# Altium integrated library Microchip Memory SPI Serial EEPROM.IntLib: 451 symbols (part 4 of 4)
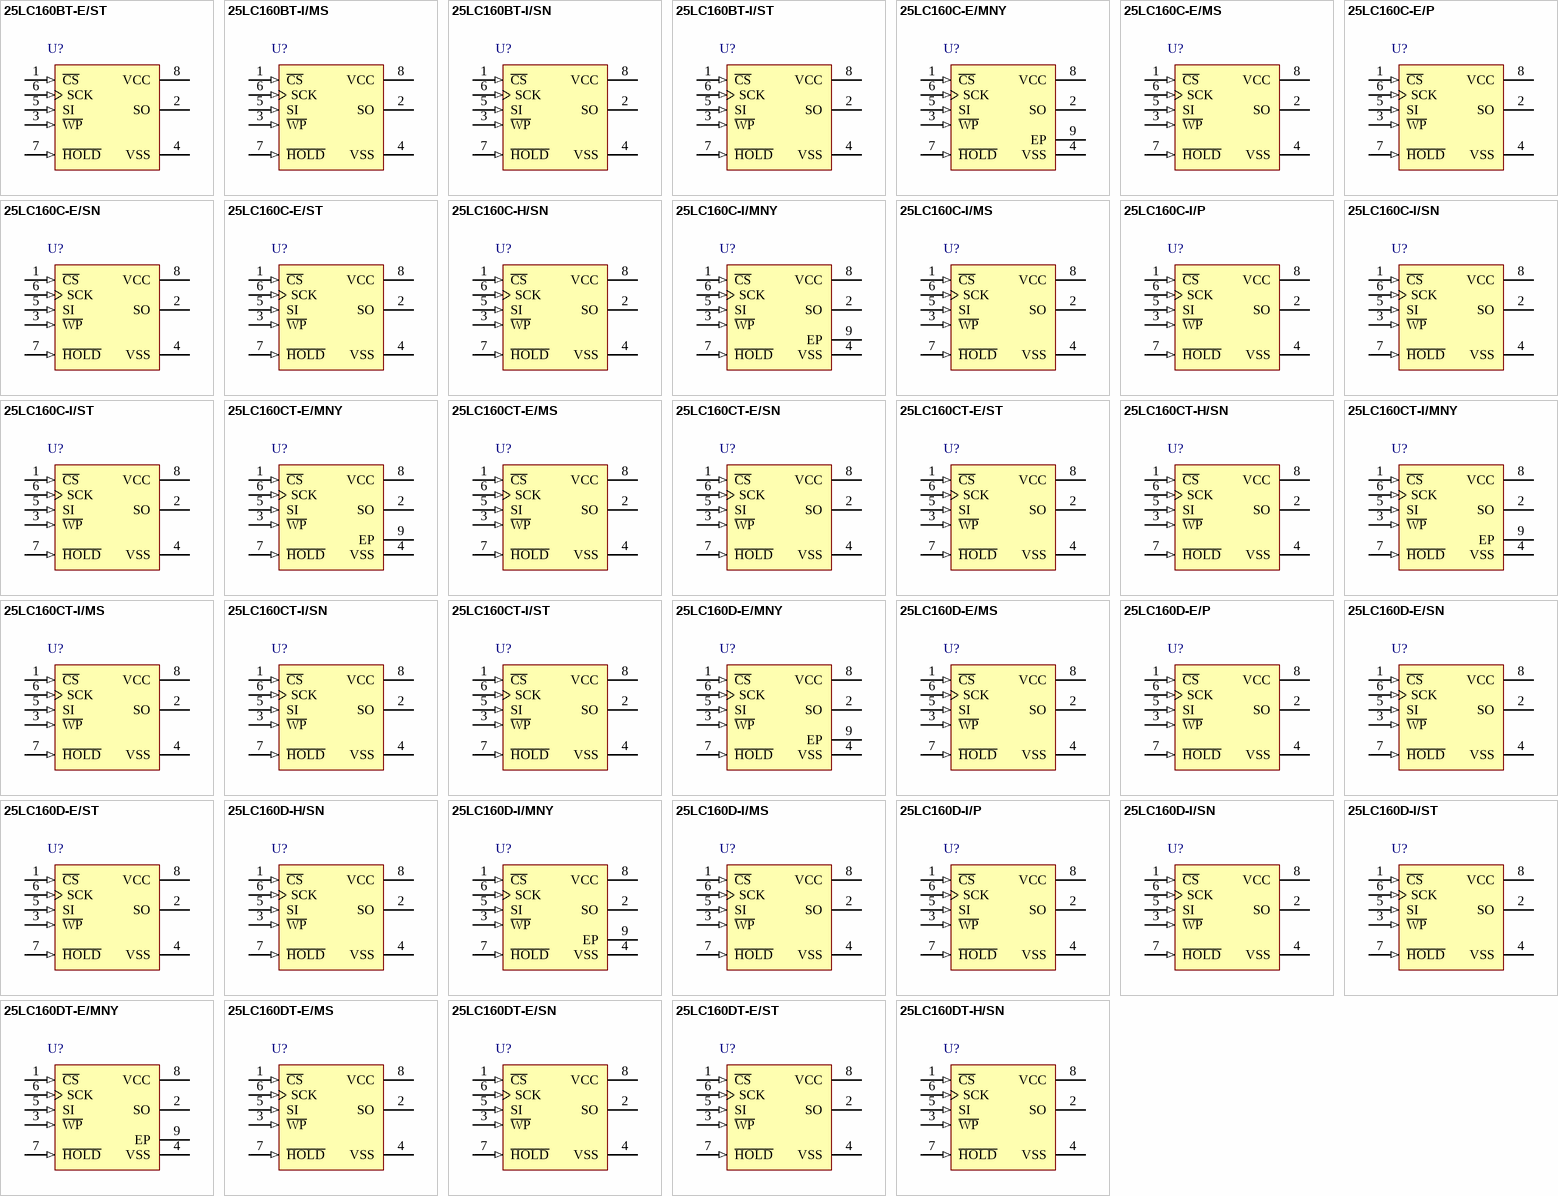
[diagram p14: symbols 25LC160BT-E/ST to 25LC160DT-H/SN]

## 25LC160C-I/ST
designator U?
16K SPI Bus Serial EEPROM, 8-Pin TSSO, Industrial Temperature
footprint TSSOP-ST8_N (TSOP, 8-Leads, Body 3x4.4mm, Pitch 0.65mm, IPC Medium Density)
footprint TSSOP-ST8_L (TSOP, 8-Leads, Body 3x4.4mm, Pitch 0.65mm, IPC High Density)
footprint TSSOP-ST8_M (TSOP, 8-Leads, Body 3x4.4mm, Pitch 0.65mm, IPC Low Density)
pins: 1 ~{CS} (in), 2 SO (hiz), 3 ~{WP} (in), 4 VSS (power), 5 SI (in), 6 SCK (in), 7 ~{HOLD} (in), 8 VCC (power)

## 25LC160CT-E/MNY
designator U?
16K SPI Bus Serial EEPROM, 8-Pin TDFN, Automotive Temperature, Tape and Reel
footprint TDFN-MN8 (SON, 8-Leads, Body 2x3mm, Pitch 0.5mm, Microchip Recommended)
pins: 1 ~{CS} (in), 2 SO (hiz), 3 ~{WP} (in), 4 VSS (power), 5 SI (in), 6 SCK (in), 7 ~{HOLD} (in), 8 VCC (power), 9 EP

## 25LC160CT-E/MS
designator U?
16K SPI Bus Serial EEPROM, 8-Pin MSOP, Automotive Temperature, Tape and Reel
footprint MSOP-MS8_N (TSOP, 8-Leads, Body 3x3mm, Pitch 0.65mm, IPC Medium Density)
footprint MSOP-MS8_L (TSOP, 8-Leads, Body 3x3mm, Pitch 0.65mm, IPC High Density)
footprint MSOP-MS8_M (TSOP, 8-Leads, Body 3x3mm, Pitch 0.65mm, IPC Low Density)
pins: 1 ~{CS} (in), 2 SO (hiz), 3 ~{WP} (in), 4 VSS (power), 5 SI (in), 6 SCK (in), 7 ~{HOLD} (in), 8 VCC (power)

## 25LC160CT-E/SN
designator U?
16K SPI Bus Serial EEPROM, 8-Pin SOIC, Automotive Temperature, Tape and Reel
footprint SOIC-SN8_N (SOIC, 8-Leads, Body 4.9x3.8mm, Pitch 1.27mm, IPC Medium Density)
footprint SOIC-SN8_L (SOIC, 8-Leads, Body 4.9x3.8mm, Pitch 1.27mm, IPC High Density)
footprint SOIC-SN8_M (SOIC, 8-Leads, Body 4.9x3.8mm, Pitch 1.27mm, IPC Low Density)
pins: 1 ~{CS} (in), 2 SO (hiz), 3 ~{WP} (in), 4 VSS (power), 5 SI (in), 6 SCK (in), 7 ~{HOLD} (in), 8 VCC (power)

## 25LC160CT-E/ST
designator U?
16K SPI Bus Serial EEPROM, 8-Pin TSSO, Automotive Temperature, Tape and Reel
footprint TSSOP-ST8_N (TSOP, 8-Leads, Body 3x4.4mm, Pitch 0.65mm, IPC Medium Density)
footprint TSSOP-ST8_L (TSOP, 8-Leads, Body 3x4.4mm, Pitch 0.65mm, IPC High Density)
footprint TSSOP-ST8_M (TSOP, 8-Leads, Body 3x4.4mm, Pitch 0.65mm, IPC Low Density)
pins: 1 ~{CS} (in), 2 SO (hiz), 3 ~{WP} (in), 4 VSS (power), 5 SI (in), 6 SCK (in), 7 ~{HOLD} (in), 8 VCC (power)

## 25LC160CT-H/SN
designator U?
16K SPI Bus Serial EEPROM, 8-Pin SOIC, Extended (High) Temperature, Tape and Reel
footprint SOIC-SN8_N (SOIC, 8-Leads, Body 4.9x3.8mm, Pitch 1.27mm, IPC Medium Density)
footprint SOIC-SN8_L (SOIC, 8-Leads, Body 4.9x3.8mm, Pitch 1.27mm, IPC High Density)
footprint SOIC-SN8_M (SOIC, 8-Leads, Body 4.9x3.8mm, Pitch 1.27mm, IPC Low Density)
pins: 1 ~{CS} (in), 2 SO (hiz), 3 ~{WP} (in), 4 VSS (power), 5 SI (in), 6 SCK (in), 7 ~{HOLD} (in), 8 VCC (power)

## 25LC160CT-I/MNY
designator U?
16K SPI Bus Serial EEPROM, 8-Pin TDFN, Industrial Temperature, Tape and Reel
footprint TDFN-MN8 (SON, 8-Leads, Body 2x3mm, Pitch 0.5mm, Microchip Recommended)
pins: 1 ~{CS} (in), 2 SO (hiz), 3 ~{WP} (in), 4 VSS (power), 5 SI (in), 6 SCK (in), 7 ~{HOLD} (in), 8 VCC (power), 9 EP

## 25LC160CT-I/MS
designator U?
16K SPI Bus Serial EEPROM, 8-Pin MSOP, Industrial Temperature, Tape and Reel
footprint MSOP-MS8_N (TSOP, 8-Leads, Body 3x3mm, Pitch 0.65mm, IPC Medium Density)
footprint MSOP-MS8_L (TSOP, 8-Leads, Body 3x3mm, Pitch 0.65mm, IPC High Density)
footprint MSOP-MS8_M (TSOP, 8-Leads, Body 3x3mm, Pitch 0.65mm, IPC Low Density)
pins: 1 ~{CS} (in), 2 SO (hiz), 3 ~{WP} (in), 4 VSS (power), 5 SI (in), 6 SCK (in), 7 ~{HOLD} (in), 8 VCC (power)

## 25LC160CT-I/SN
designator U?
16K SPI Bus Serial EEPROM, 8-Pin SOIC, Industrial Temperature, Tape and Reel
footprint SOIC-SN8_N (SOIC, 8-Leads, Body 4.9x3.8mm, Pitch 1.27mm, IPC Medium Density)
footprint SOIC-SN8_L (SOIC, 8-Leads, Body 4.9x3.8mm, Pitch 1.27mm, IPC High Density)
footprint SOIC-SN8_M (SOIC, 8-Leads, Body 4.9x3.8mm, Pitch 1.27mm, IPC Low Density)
pins: 1 ~{CS} (in), 2 SO (hiz), 3 ~{WP} (in), 4 VSS (power), 5 SI (in), 6 SCK (in), 7 ~{HOLD} (in), 8 VCC (power)

## 25LC160CT-I/ST
designator U?
16K SPI Bus Serial EEPROM, 8-Pin TSSO, Industrial Temperature, Tape and Reel
footprint TSSOP-ST8_N (TSOP, 8-Leads, Body 3x4.4mm, Pitch 0.65mm, IPC Medium Density)
footprint TSSOP-ST8_L (TSOP, 8-Leads, Body 3x4.4mm, Pitch 0.65mm, IPC High Density)
footprint TSSOP-ST8_M (TSOP, 8-Leads, Body 3x4.4mm, Pitch 0.65mm, IPC Low Density)
pins: 1 ~{CS} (in), 2 SO (hiz), 3 ~{WP} (in), 4 VSS (power), 5 SI (in), 6 SCK (in), 7 ~{HOLD} (in), 8 VCC (power)

## 25LC160D-E/MNY
designator U?
16K SPI Bus Serial EEPROM, 8-Pin TDFN, Automotive Temperature
footprint TDFN-MN8 (SON, 8-Leads, Body 2x3mm, Pitch 0.5mm, Microchip Recommended)
pins: 1 ~{CS} (in), 2 SO (hiz), 3 ~{WP} (in), 4 VSS (power), 5 SI (in), 6 SCK (in), 7 ~{HOLD} (in), 8 VCC (power), 9 EP

## 25LC160D-E/MS
designator U?
16K SPI Bus Serial EEPROM, 8-Pin MSOP, Automotive Temperature
footprint MSOP-MS8_N (TSOP, 8-Leads, Body 3x3mm, Pitch 0.65mm, IPC Medium Density)
footprint MSOP-MS8_L (TSOP, 8-Leads, Body 3x3mm, Pitch 0.65mm, IPC High Density)
footprint MSOP-MS8_M (TSOP, 8-Leads, Body 3x3mm, Pitch 0.65mm, IPC Low Density)
pins: 1 ~{CS} (in), 2 SO (hiz), 3 ~{WP} (in), 4 VSS (power), 5 SI (in), 6 SCK (in), 7 ~{HOLD} (in), 8 VCC (power)

## 25LC160D-E/P
designator U?
16K SPI Bus Serial EEPROM, 8-Pin PDIP, Automotive Temperature
footprint PDIP300-P8 (DIP, 8-Leads, Row Spacing 7.62mm, Pitch 2.54mm, Body 9.5x6.6mm)
pins: 1 ~{CS} (in), 2 SO (hiz), 3 ~{WP} (in), 4 VSS (power), 5 SI (in), 6 SCK (in), 7 ~{HOLD} (in), 8 VCC (power)

## 25LC160D-E/SN
designator U?
16K SPI Bus Serial EEPROM, 8-Pin SOIC, Automotive Temperature
footprint SOIC-SN8_N (SOIC, 8-Leads, Body 4.9x3.8mm, Pitch 1.27mm, IPC Medium Density)
footprint SOIC-SN8_L (SOIC, 8-Leads, Body 4.9x3.8mm, Pitch 1.27mm, IPC High Density)
footprint SOIC-SN8_M (SOIC, 8-Leads, Body 4.9x3.8mm, Pitch 1.27mm, IPC Low Density)
pins: 1 ~{CS} (in), 2 SO (hiz), 3 ~{WP} (in), 4 VSS (power), 5 SI (in), 6 SCK (in), 7 ~{HOLD} (in), 8 VCC (power)

## 25LC160D-E/ST
designator U?
16K SPI Bus Serial EEPROM, 8-Pin TSSO, Automotive Temperature
footprint TSSOP-ST8_N (TSOP, 8-Leads, Body 3x4.4mm, Pitch 0.65mm, IPC Medium Density)
footprint TSSOP-ST8_L (TSOP, 8-Leads, Body 3x4.4mm, Pitch 0.65mm, IPC High Density)
footprint TSSOP-ST8_M (TSOP, 8-Leads, Body 3x4.4mm, Pitch 0.65mm, IPC Low Density)
pins: 1 ~{CS} (in), 2 SO (hiz), 3 ~{WP} (in), 4 VSS (power), 5 SI (in), 6 SCK (in), 7 ~{HOLD} (in), 8 VCC (power)

## 25LC160D-H/SN
designator U?
16K SPI Bus Serial EEPROM, 8-Pin SOIC, Extended (High) Temperature
footprint SOIC-SN8_N (SOIC, 8-Leads, Body 4.9x3.8mm, Pitch 1.27mm, IPC Medium Density)
footprint SOIC-SN8_L (SOIC, 8-Leads, Body 4.9x3.8mm, Pitch 1.27mm, IPC High Density)
footprint SOIC-SN8_M (SOIC, 8-Leads, Body 4.9x3.8mm, Pitch 1.27mm, IPC Low Density)
pins: 1 ~{CS} (in), 2 SO (hiz), 3 ~{WP} (in), 4 VSS (power), 5 SI (in), 6 SCK (in), 7 ~{HOLD} (in), 8 VCC (power)

## 25LC160D-I/MNY
designator U?
16K SPI Bus Serial EEPROM, 8-Pin TDFN, Industrial Temperature
footprint TDFN-MN8 (SON, 8-Leads, Body 2x3mm, Pitch 0.5mm, Microchip Recommended)
pins: 1 ~{CS} (in), 2 SO (hiz), 3 ~{WP} (in), 4 VSS (power), 5 SI (in), 6 SCK (in), 7 ~{HOLD} (in), 8 VCC (power), 9 EP

## 25LC160D-I/MS
designator U?
16K SPI Bus Serial EEPROM, 8-Pin MSOP, Industrial Temperature
footprint MSOP-MS8_N (TSOP, 8-Leads, Body 3x3mm, Pitch 0.65mm, IPC Medium Density)
footprint MSOP-MS8_L (TSOP, 8-Leads, Body 3x3mm, Pitch 0.65mm, IPC High Density)
footprint MSOP-MS8_M (TSOP, 8-Leads, Body 3x3mm, Pitch 0.65mm, IPC Low Density)
pins: 1 ~{CS} (in), 2 SO (hiz), 3 ~{WP} (in), 4 VSS (power), 5 SI (in), 6 SCK (in), 7 ~{HOLD} (in), 8 VCC (power)

## 25LC160D-I/P
designator U?
16K SPI Bus Serial EEPROM, 8-Pin PDIP, Industrial Temperature
footprint PDIP300-P8 (DIP, 8-Leads, Row Spacing 7.62mm, Pitch 2.54mm, Body 9.5x6.6mm)
pins: 1 ~{CS} (in), 2 SO (hiz), 3 ~{WP} (in), 4 VSS (power), 5 SI (in), 6 SCK (in), 7 ~{HOLD} (in), 8 VCC (power)

## 25LC160D-I/SN
designator U?
16K SPI Bus Serial EEPROM, 8-Pin SOIC, Industrial Temperature
footprint SOIC-SN8_N (SOIC, 8-Leads, Body 4.9x3.8mm, Pitch 1.27mm, IPC Medium Density)
footprint SOIC-SN8_L (SOIC, 8-Leads, Body 4.9x3.8mm, Pitch 1.27mm, IPC High Density)
footprint SOIC-SN8_M (SOIC, 8-Leads, Body 4.9x3.8mm, Pitch 1.27mm, IPC Low Density)
pins: 1 ~{CS} (in), 2 SO (hiz), 3 ~{WP} (in), 4 VSS (power), 5 SI (in), 6 SCK (in), 7 ~{HOLD} (in), 8 VCC (power)

## 25LC160D-I/ST
designator U?
16K SPI Bus Serial EEPROM, 8-Pin TSSO, Industrial Temperature
footprint TSSOP-ST8_N (TSOP, 8-Leads, Body 3x4.4mm, Pitch 0.65mm, IPC Medium Density)
footprint TSSOP-ST8_L (TSOP, 8-Leads, Body 3x4.4mm, Pitch 0.65mm, IPC High Density)
footprint TSSOP-ST8_M (TSOP, 8-Leads, Body 3x4.4mm, Pitch 0.65mm, IPC Low Density)
pins: 1 ~{CS} (in), 2 SO (hiz), 3 ~{WP} (in), 4 VSS (power), 5 SI (in), 6 SCK (in), 7 ~{HOLD} (in), 8 VCC (power)

## 25LC160DT-E/MNY
designator U?
16K SPI Bus Serial EEPROM, 8-Pin TDFN, Automotive Temperature, Tape and Reel
footprint TDFN-MN8 (SON, 8-Leads, Body 2x3mm, Pitch 0.5mm, Microchip Recommended)
pins: 1 ~{CS} (in), 2 SO (hiz), 3 ~{WP} (in), 4 VSS (power), 5 SI (in), 6 SCK (in), 7 ~{HOLD} (in), 8 VCC (power), 9 EP

## 25LC160DT-E/MS
designator U?
16K SPI Bus Serial EEPROM, 8-Pin MSOP, Automotive Temperature, Tape and Reel
footprint MSOP-MS8_N (TSOP, 8-Leads, Body 3x3mm, Pitch 0.65mm, IPC Medium Density)
footprint MSOP-MS8_L (TSOP, 8-Leads, Body 3x3mm, Pitch 0.65mm, IPC High Density)
footprint MSOP-MS8_M (TSOP, 8-Leads, Body 3x3mm, Pitch 0.65mm, IPC Low Density)
pins: 1 ~{CS} (in), 2 SO (hiz), 3 ~{WP} (in), 4 VSS (power), 5 SI (in), 6 SCK (in), 7 ~{HOLD} (in), 8 VCC (power)

## 25LC160DT-E/SN
designator U?
16K SPI Bus Serial EEPROM, 8-Pin SOIC, Automotive Temperature, Tape and Reel
footprint SOIC-SN8_N (SOIC, 8-Leads, Body 4.9x3.8mm, Pitch 1.27mm, IPC Medium Density)
footprint SOIC-SN8_L (SOIC, 8-Leads, Body 4.9x3.8mm, Pitch 1.27mm, IPC High Density)
footprint SOIC-SN8_M (SOIC, 8-Leads, Body 4.9x3.8mm, Pitch 1.27mm, IPC Low Density)
pins: 1 ~{CS} (in), 2 SO (hiz), 3 ~{WP} (in), 4 VSS (power), 5 SI (in), 6 SCK (in), 7 ~{HOLD} (in), 8 VCC (power)

## 25LC160DT-E/ST
designator U?
16K SPI Bus Serial EEPROM, 8-Pin TSSO, Automotive Temperature, Tape and Reel
footprint TSSOP-ST8_N (TSOP, 8-Leads, Body 3x4.4mm, Pitch 0.65mm, IPC Medium Density)
footprint TSSOP-ST8_L (TSOP, 8-Leads, Body 3x4.4mm, Pitch 0.65mm, IPC High Density)
footprint TSSOP-ST8_M (TSOP, 8-Leads, Body 3x4.4mm, Pitch 0.65mm, IPC Low Density)
pins: 1 ~{CS} (in), 2 SO (hiz), 3 ~{WP} (in), 4 VSS (power), 5 SI (in), 6 SCK (in), 7 ~{HOLD} (in), 8 VCC (power)

## 25LC160DT-H/SN
designator U?
16K SPI Bus Serial EEPROM, 8-Pin SOIC, Extended (High) Temperature, Tape and Reel
footprint SOIC-SN8_N (SOIC, 8-Leads, Body 4.9x3.8mm, Pitch 1.27mm, IPC Medium Density)
footprint SOIC-SN8_L (SOIC, 8-Leads, Body 4.9x3.8mm, Pitch 1.27mm, IPC High Density)
footprint SOIC-SN8_M (SOIC, 8-Leads, Body 4.9x3.8mm, Pitch 1.27mm, IPC Low Density)
pins: 1 ~{CS} (in), 2 SO (hiz), 3 ~{WP} (in), 4 VSS (power), 5 SI (in), 6 SCK (in), 7 ~{HOLD} (in), 8 VCC (power)

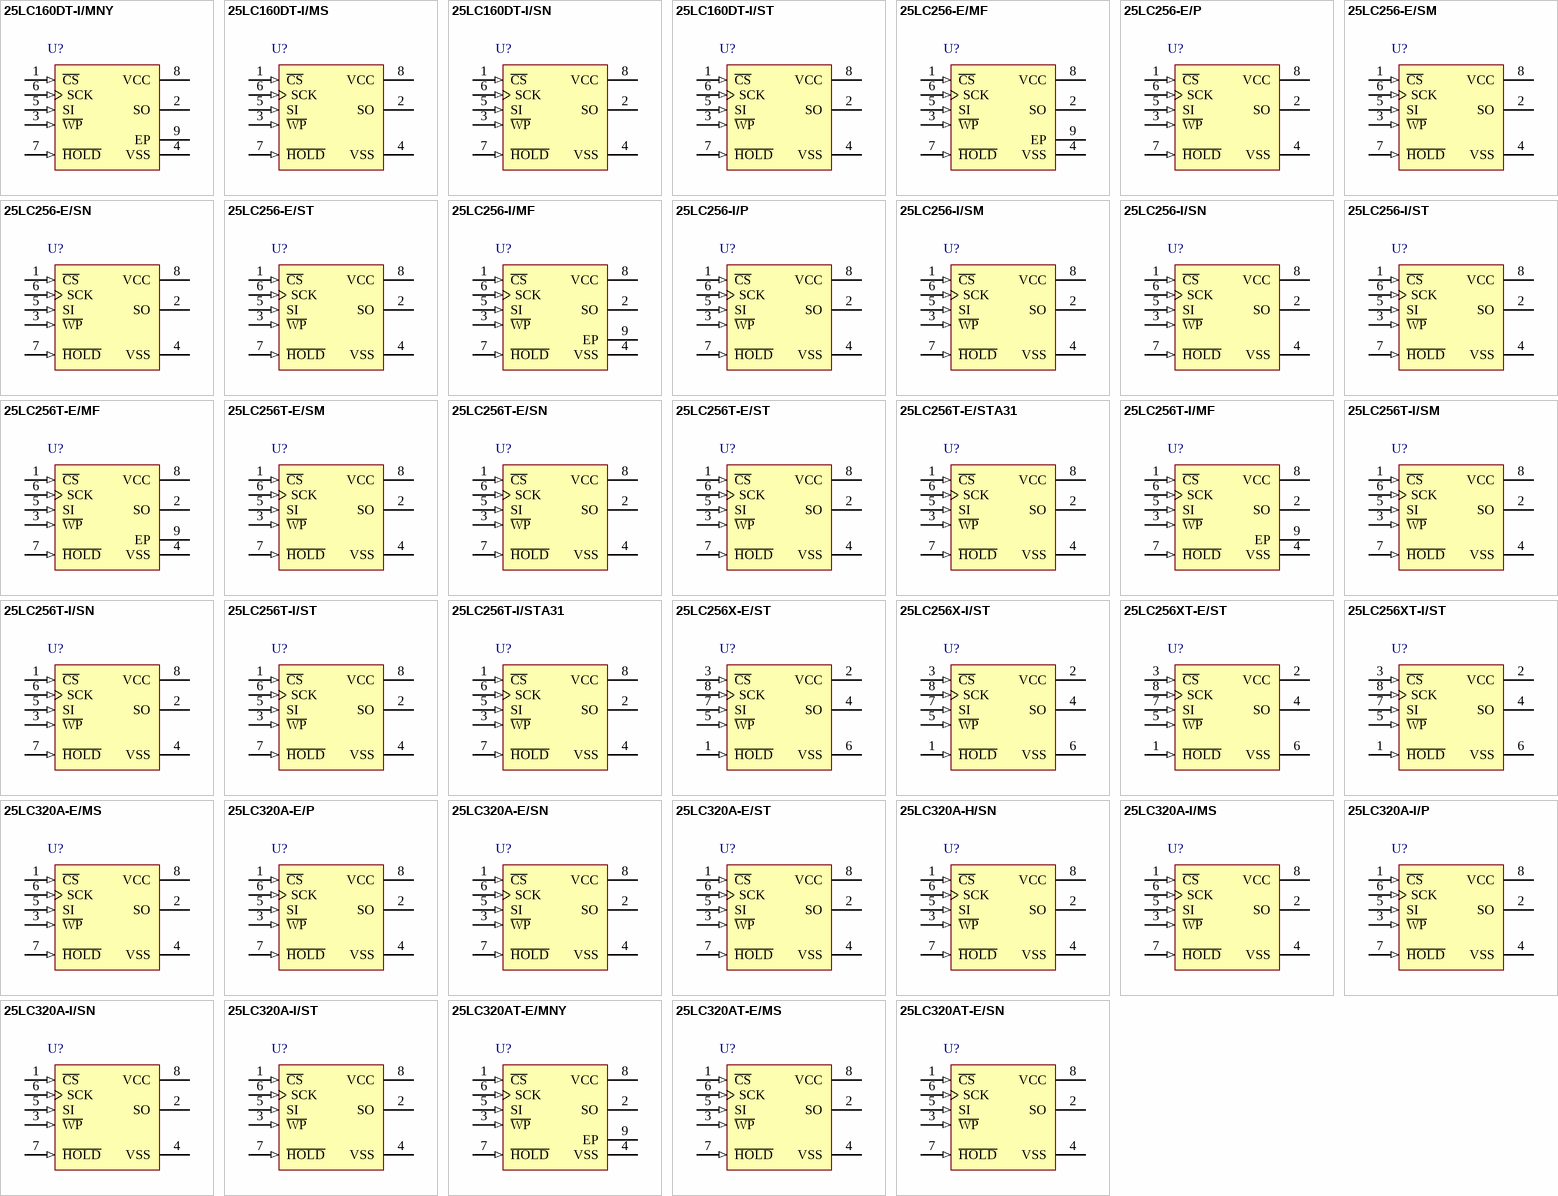
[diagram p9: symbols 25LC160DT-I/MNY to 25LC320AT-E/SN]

## 25LC160DT-I/MNY
designator U?
16K SPI Bus Serial EEPROM, 8-Pin TDFN, Industrial Temperature, Tape and Reel
footprint TDFN-MN8 (SON, 8-Leads, Body 2x3mm, Pitch 0.5mm, Microchip Recommended)
pins: 1 ~{CS} (in), 2 SO (hiz), 3 ~{WP} (in), 4 VSS (power), 5 SI (in), 6 SCK (in), 7 ~{HOLD} (in), 8 VCC (power), 9 EP

## 25LC160DT-I/MS
designator U?
16K SPI Bus Serial EEPROM, 8-Pin MSOP, Industrial Temperature, Tape and Reel
footprint MSOP-MS8_N (TSOP, 8-Leads, Body 3x3mm, Pitch 0.65mm, IPC Medium Density)
footprint MSOP-MS8_L (TSOP, 8-Leads, Body 3x3mm, Pitch 0.65mm, IPC High Density)
footprint MSOP-MS8_M (TSOP, 8-Leads, Body 3x3mm, Pitch 0.65mm, IPC Low Density)
pins: 1 ~{CS} (in), 2 SO (hiz), 3 ~{WP} (in), 4 VSS (power), 5 SI (in), 6 SCK (in), 7 ~{HOLD} (in), 8 VCC (power)

## 25LC160DT-I/SN
designator U?
16K SPI Bus Serial EEPROM, 8-Pin SOIC, Industrial Temperature, Tape and Reel
footprint SOIC-SN8_N (SOIC, 8-Leads, Body 4.9x3.8mm, Pitch 1.27mm, IPC Medium Density)
footprint SOIC-SN8_L (SOIC, 8-Leads, Body 4.9x3.8mm, Pitch 1.27mm, IPC High Density)
footprint SOIC-SN8_M (SOIC, 8-Leads, Body 4.9x3.8mm, Pitch 1.27mm, IPC Low Density)
pins: 1 ~{CS} (in), 2 SO (hiz), 3 ~{WP} (in), 4 VSS (power), 5 SI (in), 6 SCK (in), 7 ~{HOLD} (in), 8 VCC (power)

## 25LC160DT-I/ST
designator U?
16K SPI Bus Serial EEPROM, 8-Pin TSSO, Industrial Temperature, Tape and Reel
footprint TSSOP-ST8_N (TSOP, 8-Leads, Body 3x4.4mm, Pitch 0.65mm, IPC Medium Density)
footprint TSSOP-ST8_L (TSOP, 8-Leads, Body 3x4.4mm, Pitch 0.65mm, IPC High Density)
footprint TSSOP-ST8_M (TSOP, 8-Leads, Body 3x4.4mm, Pitch 0.65mm, IPC Low Density)
pins: 1 ~{CS} (in), 2 SO (hiz), 3 ~{WP} (in), 4 VSS (power), 5 SI (in), 6 SCK (in), 7 ~{HOLD} (in), 8 VCC (power)

## 25LC256-E/MF
designator U?
256K SPI Bus Serial EEPROM, 8-Pin DFN, Extended Temperature
footprint DFNS-MF8_PS (SON, 8-Leads, Body 5x6mm, Pitch 1.27mm)
pins: 1 ~{CS} (in), 2 SO (hiz), 3 ~{WP} (in), 4 VSS (power), 5 SI (in), 6 SCK (in), 7 ~{HOLD} (in), 8 VCC (power), 9 EP

## 25LC256-E/P
designator U?
256K SPI Bus Serial EEPROM, 8-Pin PDIP, Extended Temperature
footprint PDIP300-P8 (DIP, 8-Leads, Row Spacing 7.62mm, Pitch 2.54mm, Body 9.5x6.6mm)
pins: 1 ~{CS} (in), 2 SO (hiz), 3 ~{WP} (in), 4 VSS (power), 5 SI (in), 6 SCK (in), 7 ~{HOLD} (in), 8 VCC (power)

## 25LC256-E/SM
designator U?
256K SPI Bus Serial EEPROM, 8-Pin SOIC, Extended Temperature
footprint SOIJ-SM8_N (SOP, 8-Leads, Body 5.2x5.2mm, Pitch 1.27mm, IPC Medium Density)
footprint SOIJ-SM8_L (SOP, 8-Leads, Body 5.2x5.2mm, Pitch 1.27mm, IPC High Density)
footprint SOIJ-SM8_M (SOP, 8-Leads, Body 5.2x5.2mm, Pitch 1.27mm, IPC Low Density)
pins: 1 ~{CS} (in), 2 SO (hiz), 3 ~{WP} (in), 4 VSS (power), 5 SI (in), 6 SCK (in), 7 ~{HOLD} (in), 8 VCC (power)

## 25LC256-E/SN
designator U?
256K SPI Bus Serial EEPROM, 8-Pin SOIC, Extended Temperature
footprint SOIC-SN8_N (SOIC, 8-Leads, Body 4.9x3.8mm, Pitch 1.27mm, IPC Medium Density)
footprint SOIC-SN8_L (SOIC, 8-Leads, Body 4.9x3.8mm, Pitch 1.27mm, IPC High Density)
footprint SOIC-SN8_M (SOIC, 8-Leads, Body 4.9x3.8mm, Pitch 1.27mm, IPC Low Density)
pins: 1 ~{CS} (in), 2 SO (hiz), 3 ~{WP} (in), 4 VSS (power), 5 SI (in), 6 SCK (in), 7 ~{HOLD} (in), 8 VCC (power)

## 25LC256-E/ST
designator U?
256K SPI Bus Serial EEPROM, 8-Pin TSSOP, Extended Temperature
footprint TSSOP-ST8_N (TSOP, 8-Leads, Body 3x4.4mm, Pitch 0.65mm, IPC Medium Density)
footprint TSSOP-ST8_L (TSOP, 8-Leads, Body 3x4.4mm, Pitch 0.65mm, IPC High Density)
footprint TSSOP-ST8_M (TSOP, 8-Leads, Body 3x4.4mm, Pitch 0.65mm, IPC Low Density)
pins: 1 ~{CS} (in), 2 SO (hiz), 3 ~{WP} (in), 4 VSS (power), 5 SI (in), 6 SCK (in), 7 ~{HOLD} (in), 8 VCC (power)

## 25LC256-I/MF
designator U?
256K SPI Bus Serial EEPROM, 8-Pin DFN, Industrial Temperature
footprint DFNS-MF8_PS (SON, 8-Leads, Body 5x6mm, Pitch 1.27mm)
pins: 1 ~{CS} (in), 2 SO (hiz), 3 ~{WP} (in), 4 VSS (power), 5 SI (in), 6 SCK (in), 7 ~{HOLD} (in), 8 VCC (power), 9 EP

## 25LC256-I/P
designator U?
256K SPI Bus Serial EEPROM, 8-Pin PDIP, Industrial Temperature
footprint PDIP300-P8 (DIP, 8-Leads, Row Spacing 7.62mm, Pitch 2.54mm, Body 9.5x6.6mm)
pins: 1 ~{CS} (in), 2 SO (hiz), 3 ~{WP} (in), 4 VSS (power), 5 SI (in), 6 SCK (in), 7 ~{HOLD} (in), 8 VCC (power)

## 25LC256-I/SM
designator U?
256K SPI Bus Serial EEPROM, 8-Pin SOIC, Industrial Temperature
footprint SOIJ-SM8_N (SOP, 8-Leads, Body 5.2x5.2mm, Pitch 1.27mm, IPC Medium Density)
footprint SOIJ-SM8_L (SOP, 8-Leads, Body 5.2x5.2mm, Pitch 1.27mm, IPC High Density)
footprint SOIJ-SM8_M (SOP, 8-Leads, Body 5.2x5.2mm, Pitch 1.27mm, IPC Low Density)
pins: 1 ~{CS} (in), 2 SO (hiz), 3 ~{WP} (in), 4 VSS (power), 5 SI (in), 6 SCK (in), 7 ~{HOLD} (in), 8 VCC (power)

## 25LC256-I/SN
designator U?
256K SPI Bus Serial EEPROM, 8-Pin SOIC, Industrial Temperature
footprint SOIC-SN8_N (SOIC, 8-Leads, Body 4.9x3.8mm, Pitch 1.27mm, IPC Medium Density)
footprint SOIC-SN8_L (SOIC, 8-Leads, Body 4.9x3.8mm, Pitch 1.27mm, IPC High Density)
footprint SOIC-SN8_M (SOIC, 8-Leads, Body 4.9x3.8mm, Pitch 1.27mm, IPC Low Density)
pins: 1 ~{CS} (in), 2 SO (hiz), 3 ~{WP} (in), 4 VSS (power), 5 SI (in), 6 SCK (in), 7 ~{HOLD} (in), 8 VCC (power)

## 25LC256-I/ST
designator U?
256K SPI Bus Serial EEPROM, 8-Pin TSSOP, Industrial Temperature
footprint TSSOP-ST8_N (TSOP, 8-Leads, Body 3x4.4mm, Pitch 0.65mm, IPC Medium Density)
footprint TSSOP-ST8_L (TSOP, 8-Leads, Body 3x4.4mm, Pitch 0.65mm, IPC High Density)
footprint TSSOP-ST8_M (TSOP, 8-Leads, Body 3x4.4mm, Pitch 0.65mm, IPC Low Density)
pins: 1 ~{CS} (in), 2 SO (hiz), 3 ~{WP} (in), 4 VSS (power), 5 SI (in), 6 SCK (in), 7 ~{HOLD} (in), 8 VCC (power)

## 25LC256T-E/MF
designator U?
256K SPI Bus Serial EEPROM, 8-Pin DFN, Extended Temperature, Tape and Reel
footprint DFNS-MF8_PS (SON, 8-Leads, Body 5x6mm, Pitch 1.27mm)
pins: 1 ~{CS} (in), 2 SO (hiz), 3 ~{WP} (in), 4 VSS (power), 5 SI (in), 6 SCK (in), 7 ~{HOLD} (in), 8 VCC (power), 9 EP

## 25LC256T-E/SM
designator U?
256K SPI Bus Serial EEPROM, 8-Pin SOIC, Extended Temperature, Tape and Reel
footprint SOIJ-SM8_N (SOP, 8-Leads, Body 5.2x5.2mm, Pitch 1.27mm, IPC Medium Density)
footprint SOIJ-SM8_L (SOP, 8-Leads, Body 5.2x5.2mm, Pitch 1.27mm, IPC High Density)
footprint SOIJ-SM8_M (SOP, 8-Leads, Body 5.2x5.2mm, Pitch 1.27mm, IPC Low Density)
pins: 1 ~{CS} (in), 2 SO (hiz), 3 ~{WP} (in), 4 VSS (power), 5 SI (in), 6 SCK (in), 7 ~{HOLD} (in), 8 VCC (power)

## 25LC256T-E/SN
designator U?
256K SPI Bus Serial EEPROM, 8-Pin SOIC, Extended Temperature, Tape and Reel
footprint SOIC-SN8_N (SOIC, 8-Leads, Body 4.9x3.8mm, Pitch 1.27mm, IPC Medium Density)
footprint SOIC-SN8_L (SOIC, 8-Leads, Body 4.9x3.8mm, Pitch 1.27mm, IPC High Density)
footprint SOIC-SN8_M (SOIC, 8-Leads, Body 4.9x3.8mm, Pitch 1.27mm, IPC Low Density)
pins: 1 ~{CS} (in), 2 SO (hiz), 3 ~{WP} (in), 4 VSS (power), 5 SI (in), 6 SCK (in), 7 ~{HOLD} (in), 8 VCC (power)

## 25LC256T-E/ST
designator U?
256K SPI Bus Serial EEPROM, 8-Pin TSSOP, Extended Temperature, Tape and Reel
footprint TSSOP-ST8_N (TSOP, 8-Leads, Body 3x4.4mm, Pitch 0.65mm, IPC Medium Density)
footprint TSSOP-ST8_L (TSOP, 8-Leads, Body 3x4.4mm, Pitch 0.65mm, IPC High Density)
footprint TSSOP-ST8_M (TSOP, 8-Leads, Body 3x4.4mm, Pitch 0.65mm, IPC Low Density)
pins: 1 ~{CS} (in), 2 SO (hiz), 3 ~{WP} (in), 4 VSS (power), 5 SI (in), 6 SCK (in), 7 ~{HOLD} (in), 8 VCC (power)

## 25LC256T-E/STA31
designator U?
256K SPI Bus Serial EEPROM, 8-Pin TSSOP, Extended Temperature, Tape and Reel
footprint TSSOP-ST8_N (TSOP, 8-Leads, Body 3x4.4mm, Pitch 0.65mm, IPC Medium Density)
footprint TSSOP-ST8_L (TSOP, 8-Leads, Body 3x4.4mm, Pitch 0.65mm, IPC High Density)
footprint TSSOP-ST8_M (TSOP, 8-Leads, Body 3x4.4mm, Pitch 0.65mm, IPC Low Density)
pins: 1 ~{CS} (in), 2 SO (hiz), 3 ~{WP} (in), 4 VSS (power), 5 SI (in), 6 SCK (in), 7 ~{HOLD} (in), 8 VCC (power)

## 25LC256T-I/MF
designator U?
256K SPI Bus Serial EEPROM, 8-Pin DFN, Industrial Temperature, Tape and Reel
footprint DFNS-MF8_PS (SON, 8-Leads, Body 5x6mm, Pitch 1.27mm)
pins: 1 ~{CS} (in), 2 SO (hiz), 3 ~{WP} (in), 4 VSS (power), 5 SI (in), 6 SCK (in), 7 ~{HOLD} (in), 8 VCC (power), 9 EP

## 25LC256T-I/SM
designator U?
256K SPI Bus Serial EEPROM, 8-Pin SOIC, Industrial Temperature, Tape and Reel
footprint SOIJ-SM8_N (SOP, 8-Leads, Body 5.2x5.2mm, Pitch 1.27mm, IPC Medium Density)
footprint SOIJ-SM8_L (SOP, 8-Leads, Body 5.2x5.2mm, Pitch 1.27mm, IPC High Density)
footprint SOIJ-SM8_M (SOP, 8-Leads, Body 5.2x5.2mm, Pitch 1.27mm, IPC Low Density)
pins: 1 ~{CS} (in), 2 SO (hiz), 3 ~{WP} (in), 4 VSS (power), 5 SI (in), 6 SCK (in), 7 ~{HOLD} (in), 8 VCC (power)

## 25LC256T-I/SN
designator U?
256K SPI Bus Serial EEPROM, 8-Pin SOIC, Industrial Temperature, Tape and Reel
footprint SOIC-SN8_N (SOIC, 8-Leads, Body 4.9x3.8mm, Pitch 1.27mm, IPC Medium Density)
footprint SOIC-SN8_L (SOIC, 8-Leads, Body 4.9x3.8mm, Pitch 1.27mm, IPC High Density)
footprint SOIC-SN8_M (SOIC, 8-Leads, Body 4.9x3.8mm, Pitch 1.27mm, IPC Low Density)
pins: 1 ~{CS} (in), 2 SO (hiz), 3 ~{WP} (in), 4 VSS (power), 5 SI (in), 6 SCK (in), 7 ~{HOLD} (in), 8 VCC (power)

## 25LC256T-I/ST
designator U?
256K SPI Bus Serial EEPROM, 8-Pin TSSOP, Industrial Temperature, Tape and Reel
footprint TSSOP-ST8_N (TSOP, 8-Leads, Body 3x4.4mm, Pitch 0.65mm, IPC Medium Density)
footprint TSSOP-ST8_L (TSOP, 8-Leads, Body 3x4.4mm, Pitch 0.65mm, IPC High Density)
footprint TSSOP-ST8_M (TSOP, 8-Leads, Body 3x4.4mm, Pitch 0.65mm, IPC Low Density)
pins: 1 ~{CS} (in), 2 SO (hiz), 3 ~{WP} (in), 4 VSS (power), 5 SI (in), 6 SCK (in), 7 ~{HOLD} (in), 8 VCC (power)

## 25LC256T-I/STA31
designator U?
256K SPI Bus Serial EEPROM, 8-Pin TSSOP, Industrial Temperature, Tape and Reel
footprint TSSOP-ST8_N (TSOP, 8-Leads, Body 3x4.4mm, Pitch 0.65mm, IPC Medium Density)
footprint TSSOP-ST8_L (TSOP, 8-Leads, Body 3x4.4mm, Pitch 0.65mm, IPC High Density)
footprint TSSOP-ST8_M (TSOP, 8-Leads, Body 3x4.4mm, Pitch 0.65mm, IPC Low Density)
pins: 1 ~{CS} (in), 2 SO (hiz), 3 ~{WP} (in), 4 VSS (power), 5 SI (in), 6 SCK (in), 7 ~{HOLD} (in), 8 VCC (power)

## 25LC256X-E/ST
designator U?
256K SPI Bus Serial EEPROM, 8-Pin TSSOP, Extended Temperature
footprint TSSOP-ST8_N (TSOP, 8-Leads, Body 3x4.4mm, Pitch 0.65mm, IPC Medium Density)
footprint TSSOP-ST8_L (TSOP, 8-Leads, Body 3x4.4mm, Pitch 0.65mm, IPC High Density)
footprint TSSOP-ST8_M (TSOP, 8-Leads, Body 3x4.4mm, Pitch 0.65mm, IPC Low Density)
pins: 1 ~{HOLD} (in), 2 VCC (power), 3 ~{CS} (in), 4 SO (hiz), 5 ~{WP} (in), 6 VSS (power), 7 SI (in), 8 SCK (in)

## 25LC256X-I/ST
designator U?
256K SPI Bus Serial EEPROM, 8-Pin TSSOP, Industrial Temperature
footprint TSSOP-ST8_N (TSOP, 8-Leads, Body 3x4.4mm, Pitch 0.65mm, IPC Medium Density)
footprint TSSOP-ST8_L (TSOP, 8-Leads, Body 3x4.4mm, Pitch 0.65mm, IPC High Density)
footprint TSSOP-ST8_M (TSOP, 8-Leads, Body 3x4.4mm, Pitch 0.65mm, IPC Low Density)
pins: 1 ~{HOLD} (in), 2 VCC (power), 3 ~{CS} (in), 4 SO (hiz), 5 ~{WP} (in), 6 VSS (power), 7 SI (in), 8 SCK (in)

## 25LC256XT-E/ST
designator U?
256K SPI Bus Serial EEPROM, 8-Pin TSSOP, Extended Temperature, Tape and Reel
footprint TSSOP-ST8_N (TSOP, 8-Leads, Body 3x4.4mm, Pitch 0.65mm, IPC Medium Density)
footprint TSSOP-ST8_L (TSOP, 8-Leads, Body 3x4.4mm, Pitch 0.65mm, IPC High Density)
footprint TSSOP-ST8_M (TSOP, 8-Leads, Body 3x4.4mm, Pitch 0.65mm, IPC Low Density)
pins: 1 ~{HOLD} (in), 2 VCC (power), 3 ~{CS} (in), 4 SO (hiz), 5 ~{WP} (in), 6 VSS (power), 7 SI (in), 8 SCK (in)

## 25LC256XT-I/ST
designator U?
256K SPI Bus Serial EEPROM, 8-Pin TSSOP, Industrial Temperature, Tape and Reel
footprint TSSOP-ST8_N (TSOP, 8-Leads, Body 3x4.4mm, Pitch 0.65mm, IPC Medium Density)
footprint TSSOP-ST8_L (TSOP, 8-Leads, Body 3x4.4mm, Pitch 0.65mm, IPC High Density)
footprint TSSOP-ST8_M (TSOP, 8-Leads, Body 3x4.4mm, Pitch 0.65mm, IPC Low Density)
pins: 1 ~{HOLD} (in), 2 VCC (power), 3 ~{CS} (in), 4 SO (hiz), 5 ~{WP} (in), 6 VSS (power), 7 SI (in), 8 SCK (in)

## 25LC320A-E/MS
designator U?
32K SPI Bus Serial EEPROM, 8-Pin MSOP, Extended Temperature
footprint MSOP-MS8_N (TSOP, 8-Leads, Body 3x3mm, Pitch 0.65mm, IPC Medium Density)
footprint MSOP-MS8_L (TSOP, 8-Leads, Body 3x3mm, Pitch 0.65mm, IPC High Density)
footprint MSOP-MS8_M (TSOP, 8-Leads, Body 3x3mm, Pitch 0.65mm, IPC Low Density)
pins: 1 ~{CS} (in), 2 SO (hiz), 3 ~{WP} (in), 4 VSS (power), 5 SI (in), 6 SCK (in), 7 ~{HOLD} (in), 8 VCC (power)

## 25LC320A-E/P
designator U?
32K SPI Bus Serial EEPROM, 8-Pin PDIP, Extended Temperature
footprint PDIP300-P8 (DIP, 8-Leads, Row Spacing 7.62mm, Pitch 2.54mm, Body 9.5x6.6mm)
pins: 1 ~{CS} (in), 2 SO (hiz), 3 ~{WP} (in), 4 VSS (power), 5 SI (in), 6 SCK (in), 7 ~{HOLD} (in), 8 VCC (power)

## 25LC320A-E/SN
designator U?
32K SPI Bus Serial EEPROM, 8-Pin SOIC, Extended Temperature
footprint SOIC-SN8_N (SOIC, 8-Leads, Body 4.9x3.8mm, Pitch 1.27mm, IPC Medium Density)
footprint SOIC-SN8_L (SOIC, 8-Leads, Body 4.9x3.8mm, Pitch 1.27mm, IPC High Density)
footprint SOIC-SN8_M (SOIC, 8-Leads, Body 4.9x3.8mm, Pitch 1.27mm, IPC Low Density)
pins: 1 ~{CS} (in), 2 SO (hiz), 3 ~{WP} (in), 4 VSS (power), 5 SI (in), 6 SCK (in), 7 ~{HOLD} (in), 8 VCC (power)

## 25LC320A-E/ST
designator U?
32K SPI Bus Serial EEPROM, 8-Pin TSSOP, Extended Temperature
footprint TSSOP-ST8_N (TSOP, 8-Leads, Body 3x4.4mm, Pitch 0.65mm, IPC Medium Density)
footprint TSSOP-ST8_L (TSOP, 8-Leads, Body 3x4.4mm, Pitch 0.65mm, IPC High Density)
footprint TSSOP-ST8_M (TSOP, 8-Leads, Body 3x4.4mm, Pitch 0.65mm, IPC Low Density)
pins: 1 ~{CS} (in), 2 SO (hiz), 3 ~{WP} (in), 4 VSS (power), 5 SI (in), 6 SCK (in), 7 ~{HOLD} (in), 8 VCC (power)

## 25LC320A-H/SN
designator U?
32K SPI Bus Serial EEPROM, 8-Pin SOIC, Extended (High) Temperature
footprint SOIC-SN8_N (SOIC, 8-Leads, Body 4.9x3.8mm, Pitch 1.27mm, IPC Medium Density)
footprint SOIC-SN8_L (SOIC, 8-Leads, Body 4.9x3.8mm, Pitch 1.27mm, IPC High Density)
footprint SOIC-SN8_M (SOIC, 8-Leads, Body 4.9x3.8mm, Pitch 1.27mm, IPC Low Density)
pins: 1 ~{CS} (in), 2 SO (hiz), 3 ~{WP} (in), 4 VSS (power), 5 SI (in), 6 SCK (in), 7 ~{HOLD} (in), 8 VCC (power)

## 25LC320A-I/MS
designator U?
32K SPI Bus Serial EEPROM, 8-Pin MSOP, Industrial Temperature
footprint MSOP-MS8_N (TSOP, 8-Leads, Body 3x3mm, Pitch 0.65mm, IPC Medium Density)
footprint MSOP-MS8_L (TSOP, 8-Leads, Body 3x3mm, Pitch 0.65mm, IPC High Density)
footprint MSOP-MS8_M (TSOP, 8-Leads, Body 3x3mm, Pitch 0.65mm, IPC Low Density)
pins: 1 ~{CS} (in), 2 SO (hiz), 3 ~{WP} (in), 4 VSS (power), 5 SI (in), 6 SCK (in), 7 ~{HOLD} (in), 8 VCC (power)

## 25LC320A-I/P
designator U?
32K SPI Bus Serial EEPROM, 8-Pin PDIP, Industrial Temperature
footprint PDIP300-P8 (DIP, 8-Leads, Row Spacing 7.62mm, Pitch 2.54mm, Body 9.5x6.6mm)
pins: 1 ~{CS} (in), 2 SO (hiz), 3 ~{WP} (in), 4 VSS (power), 5 SI (in), 6 SCK (in), 7 ~{HOLD} (in), 8 VCC (power)

## 25LC320A-I/SN
designator U?
32K SPI Bus Serial EEPROM, 8-Pin SOIC, Industrial Temperature
footprint SOIC-SN8_N (SOIC, 8-Leads, Body 4.9x3.8mm, Pitch 1.27mm, IPC Medium Density)
footprint SOIC-SN8_L (SOIC, 8-Leads, Body 4.9x3.8mm, Pitch 1.27mm, IPC High Density)
footprint SOIC-SN8_M (SOIC, 8-Leads, Body 4.9x3.8mm, Pitch 1.27mm, IPC Low Density)
pins: 1 ~{CS} (in), 2 SO (hiz), 3 ~{WP} (in), 4 VSS (power), 5 SI (in), 6 SCK (in), 7 ~{HOLD} (in), 8 VCC (power)

## 25LC320A-I/ST
designator U?
32K SPI Bus Serial EEPROM, 8-Pin TSSOP, Industrial Temperature
footprint TSSOP-ST8_N (TSOP, 8-Leads, Body 3x4.4mm, Pitch 0.65mm, IPC Medium Density)
footprint TSSOP-ST8_L (TSOP, 8-Leads, Body 3x4.4mm, Pitch 0.65mm, IPC High Density)
footprint TSSOP-ST8_M (TSOP, 8-Leads, Body 3x4.4mm, Pitch 0.65mm, IPC Low Density)
pins: 1 ~{CS} (in), 2 SO (hiz), 3 ~{WP} (in), 4 VSS (power), 5 SI (in), 6 SCK (in), 7 ~{HOLD} (in), 8 VCC (power)

## 25LC320AT-E/MNY
designator U?
32K SPI Bus Serial EEPROM, 8-Pin TDFN, Automotive Temperature, Tape and Reel
footprint TDFN-MN8 (SON, 8-Leads, Body 2x3mm, Pitch 0.5mm, Microchip Recommended)
pins: 1 ~{CS} (in), 2 SO (hiz), 3 ~{WP} (in), 4 VSS (power), 5 SI (in), 6 SCK (in), 7 ~{HOLD} (in), 8 VCC (power), 9 EP

## 25LC320AT-E/MS
designator U?
32K SPI Bus Serial EEPROM, 8-Pin MSOP, Extended Temperature, Tape and Reel
footprint MSOP-MS8_N (TSOP, 8-Leads, Body 3x3mm, Pitch 0.65mm, IPC Medium Density)
footprint MSOP-MS8_L (TSOP, 8-Leads, Body 3x3mm, Pitch 0.65mm, IPC High Density)
footprint MSOP-MS8_M (TSOP, 8-Leads, Body 3x3mm, Pitch 0.65mm, IPC Low Density)
pins: 1 ~{CS} (in), 2 SO (hiz), 3 ~{WP} (in), 4 VSS (power), 5 SI (in), 6 SCK (in), 7 ~{HOLD} (in), 8 VCC (power)

## 25LC320AT-E/SN
designator U?
32K SPI Bus Serial EEPROM, 8-Pin SOIC, Extended Temperature, Tape and Reel
footprint SOIC-SN8_N (SOIC, 8-Leads, Body 4.9x3.8mm, Pitch 1.27mm, IPC Medium Density)
footprint SOIC-SN8_L (SOIC, 8-Leads, Body 4.9x3.8mm, Pitch 1.27mm, IPC High Density)
footprint SOIC-SN8_M (SOIC, 8-Leads, Body 4.9x3.8mm, Pitch 1.27mm, IPC Low Density)
pins: 1 ~{CS} (in), 2 SO (hiz), 3 ~{WP} (in), 4 VSS (power), 5 SI (in), 6 SCK (in), 7 ~{HOLD} (in), 8 VCC (power)

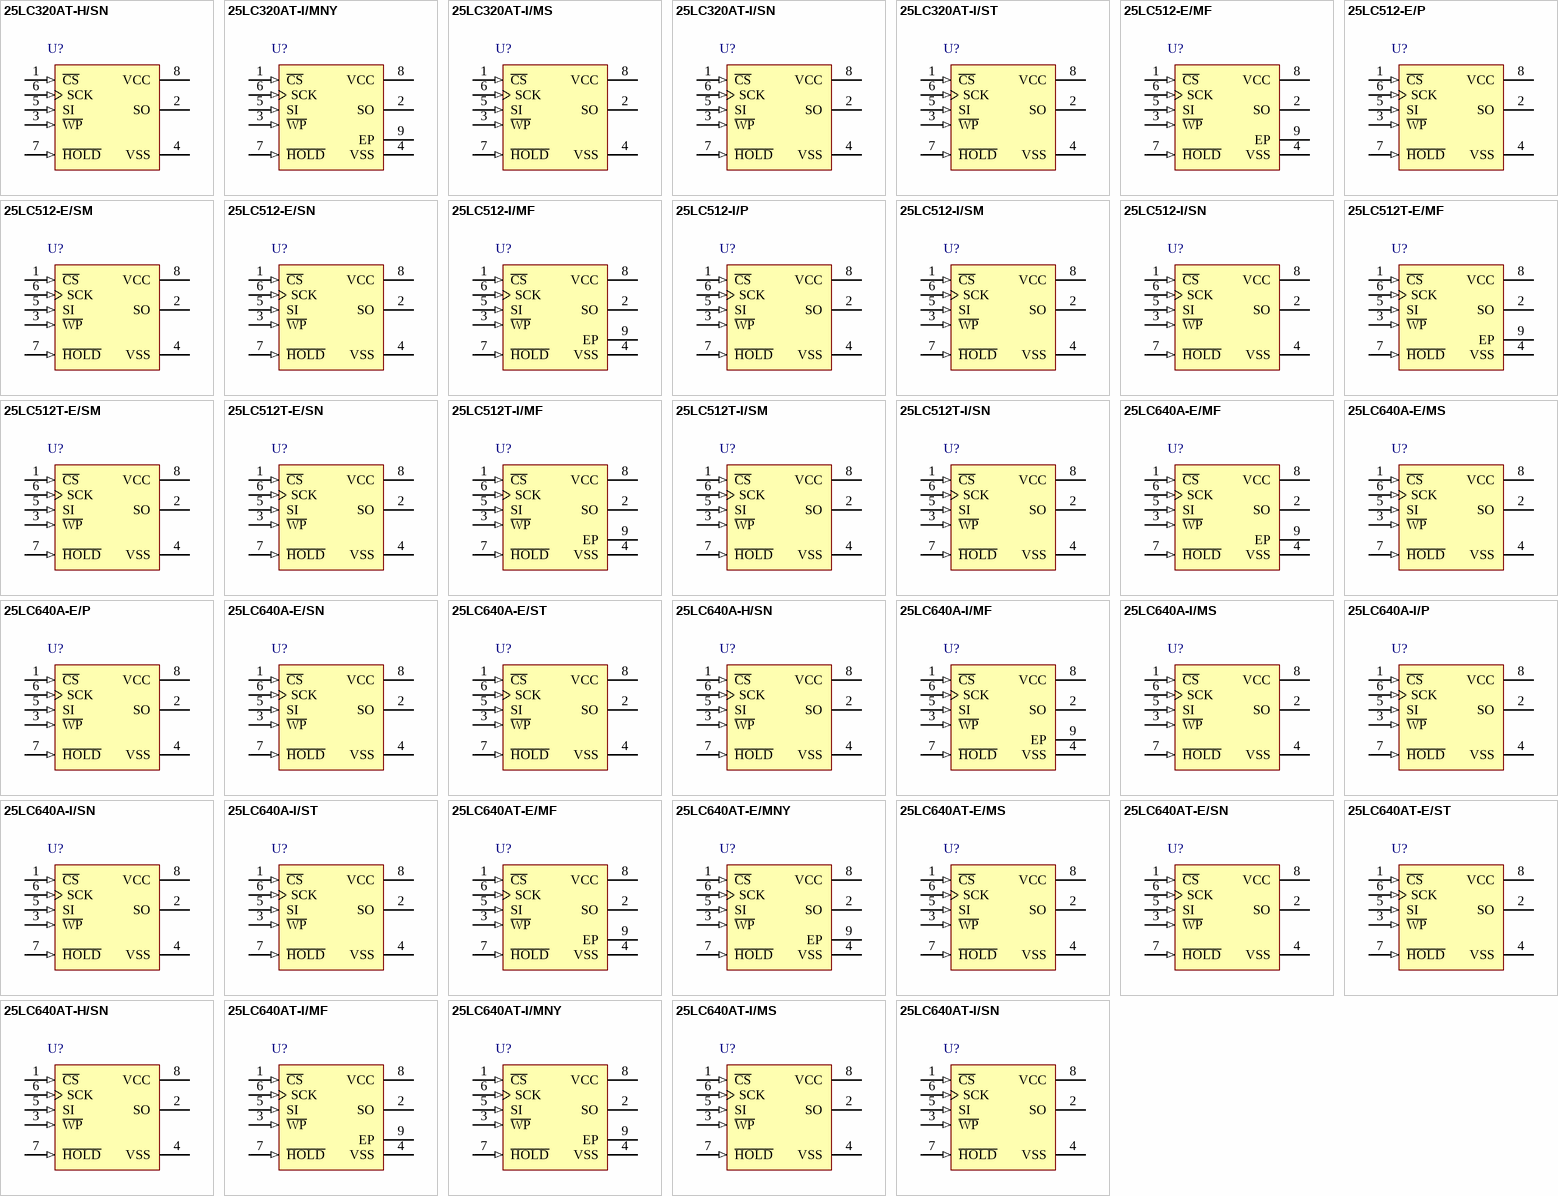
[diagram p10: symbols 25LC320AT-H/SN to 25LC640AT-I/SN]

## 25LC320AT-H/SN
designator U?
32K SPI Bus Serial EEPROM, 8-Pin SOIC, Extended (High) Temperature, Tape and Reel
footprint SOIC-SN8_N (SOIC, 8-Leads, Body 4.9x3.8mm, Pitch 1.27mm, IPC Medium Density)
footprint SOIC-SN8_L (SOIC, 8-Leads, Body 4.9x3.8mm, Pitch 1.27mm, IPC High Density)
footprint SOIC-SN8_M (SOIC, 8-Leads, Body 4.9x3.8mm, Pitch 1.27mm, IPC Low Density)
pins: 1 ~{CS} (in), 2 SO (hiz), 3 ~{WP} (in), 4 VSS (power), 5 SI (in), 6 SCK (in), 7 ~{HOLD} (in), 8 VCC (power)

## 25LC320AT-I/MNY
designator U?
32K SPI Bus Serial EEPROM, 8-Pin TDFN, Industrial Temperature, Tape and Reel
footprint TDFN-MN8 (SON, 8-Leads, Body 2x3mm, Pitch 0.5mm, Microchip Recommended)
pins: 1 ~{CS} (in), 2 SO (hiz), 3 ~{WP} (in), 4 VSS (power), 5 SI (in), 6 SCK (in), 7 ~{HOLD} (in), 8 VCC (power), 9 EP

## 25LC320AT-I/MS
designator U?
32K SPI Bus Serial EEPROM, 8-Pin MSOP, Industrial Temperature, Tape and Reel
footprint MSOP-MS8_N (TSOP, 8-Leads, Body 3x3mm, Pitch 0.65mm, IPC Medium Density)
footprint MSOP-MS8_L (TSOP, 8-Leads, Body 3x3mm, Pitch 0.65mm, IPC High Density)
footprint MSOP-MS8_M (TSOP, 8-Leads, Body 3x3mm, Pitch 0.65mm, IPC Low Density)
pins: 1 ~{CS} (in), 2 SO (hiz), 3 ~{WP} (in), 4 VSS (power), 5 SI (in), 6 SCK (in), 7 ~{HOLD} (in), 8 VCC (power)

## 25LC320AT-I/SN
designator U?
32K SPI Bus Serial EEPROM, 8-Pin SOIC, Industrial Temperature, Tape and Reel
footprint SOIC-SN8_N (SOIC, 8-Leads, Body 4.9x3.8mm, Pitch 1.27mm, IPC Medium Density)
footprint SOIC-SN8_L (SOIC, 8-Leads, Body 4.9x3.8mm, Pitch 1.27mm, IPC High Density)
footprint SOIC-SN8_M (SOIC, 8-Leads, Body 4.9x3.8mm, Pitch 1.27mm, IPC Low Density)
pins: 1 ~{CS} (in), 2 SO (hiz), 3 ~{WP} (in), 4 VSS (power), 5 SI (in), 6 SCK (in), 7 ~{HOLD} (in), 8 VCC (power)

## 25LC320AT-I/ST
designator U?
32K SPI Bus Serial EEPROM, 8-Pin TSSOP, Industrial Temperature, Tape and Reel
footprint TSSOP-ST8_N (TSOP, 8-Leads, Body 3x4.4mm, Pitch 0.65mm, IPC Medium Density)
footprint TSSOP-ST8_L (TSOP, 8-Leads, Body 3x4.4mm, Pitch 0.65mm, IPC High Density)
footprint TSSOP-ST8_M (TSOP, 8-Leads, Body 3x4.4mm, Pitch 0.65mm, IPC Low Density)
pins: 1 ~{CS} (in), 2 SO (hiz), 3 ~{WP} (in), 4 VSS (power), 5 SI (in), 6 SCK (in), 7 ~{HOLD} (in), 8 VCC (power)

## 25LC512-E/MF
designator U?
512 Kbit SPI Bus Serial EEPROM, 8-Pin DFN, Extended Temperature
footprint DFNS-MF8_PS (SON, 8-Leads, Body 5x6mm, Pitch 1.27mm)
pins: 1 ~{CS} (in), 2 SO (hiz), 3 ~{WP} (in), 4 VSS (power), 5 SI (in), 6 SCK (in), 7 ~{HOLD} (in), 8 VCC (power), 9 EP

## 25LC512-E/P
designator U?
512 Kbit SPI Bus Serial EEPROM, 8-Pin PDIP, Extended Temperature
footprint PDIP300-P8 (DIP, 8-Leads, Row Spacing 7.62mm, Pitch 2.54mm, Body 9.5x6.6mm)
pins: 1 ~{CS} (in), 2 SO (hiz), 3 ~{WP} (in), 4 VSS (power), 5 SI (in), 6 SCK (in), 7 ~{HOLD} (in), 8 VCC (power)

## 25LC512-E/SM
designator U?
512 Kbit SPI Bus Serial EEPROM, 8-Pin SOIC, Extended Temperature
footprint SOIJ-SM8_N (SOP, 8-Leads, Body 5.2x5.2mm, Pitch 1.27mm, IPC Medium Density)
footprint SOIJ-SM8_L (SOP, 8-Leads, Body 5.2x5.2mm, Pitch 1.27mm, IPC High Density)
footprint SOIJ-SM8_M (SOP, 8-Leads, Body 5.2x5.2mm, Pitch 1.27mm, IPC Low Density)
pins: 1 ~{CS} (in), 2 SO (hiz), 3 ~{WP} (in), 4 VSS (power), 5 SI (in), 6 SCK (in), 7 ~{HOLD} (in), 8 VCC (power)

## 25LC512-E/SN
designator U?
512 Kbit SPI Bus Serial EEPROM, 8-Pin SOIC, Extended Temperature
footprint SOIC-SN8_N (SOIC, 8-Leads, Body 4.9x3.8mm, Pitch 1.27mm, IPC Medium Density)
footprint SOIC-SN8_L (SOIC, 8-Leads, Body 4.9x3.8mm, Pitch 1.27mm, IPC High Density)
footprint SOIC-SN8_M (SOIC, 8-Leads, Body 4.9x3.8mm, Pitch 1.27mm, IPC Low Density)
pins: 1 ~{CS} (in), 2 SO (hiz), 3 ~{WP} (in), 4 VSS (power), 5 SI (in), 6 SCK (in), 7 ~{HOLD} (in), 8 VCC (power)

## 25LC512-I/MF
designator U?
512 Kbit SPI Bus Serial EEPROM, 8-Pin DFN, Industrial Temperature
footprint DFNS-MF8_PS (SON, 8-Leads, Body 5x6mm, Pitch 1.27mm)
pins: 1 ~{CS} (in), 2 SO (hiz), 3 ~{WP} (in), 4 VSS (power), 5 SI (in), 6 SCK (in), 7 ~{HOLD} (in), 8 VCC (power), 9 EP

## 25LC512-I/P
designator U?
512 Kbit SPI Bus Serial EEPROM, 8-Pin PDIP, Industrial Temperature
footprint PDIP300-P8 (DIP, 8-Leads, Row Spacing 7.62mm, Pitch 2.54mm, Body 9.5x6.6mm)
pins: 1 ~{CS} (in), 2 SO (hiz), 3 ~{WP} (in), 4 VSS (power), 5 SI (in), 6 SCK (in), 7 ~{HOLD} (in), 8 VCC (power)

## 25LC512-I/SM
designator U?
512 Kbit SPI Bus Serial EEPROM, 8-Pin SOIC, Industrial Temperature
footprint SOIJ-SM8_N (SOP, 8-Leads, Body 5.2x5.2mm, Pitch 1.27mm, IPC Medium Density)
footprint SOIJ-SM8_L (SOP, 8-Leads, Body 5.2x5.2mm, Pitch 1.27mm, IPC High Density)
footprint SOIJ-SM8_M (SOP, 8-Leads, Body 5.2x5.2mm, Pitch 1.27mm, IPC Low Density)
pins: 1 ~{CS} (in), 2 SO (hiz), 3 ~{WP} (in), 4 VSS (power), 5 SI (in), 6 SCK (in), 7 ~{HOLD} (in), 8 VCC (power)

## 25LC512-I/SN
designator U?
512 Kbit SPI Bus Serial EEPROM, 8-Pin SOIC, Industrial Temperature
footprint SOIC-SN8_N (SOIC, 8-Leads, Body 4.9x3.8mm, Pitch 1.27mm, IPC Medium Density)
footprint SOIC-SN8_L (SOIC, 8-Leads, Body 4.9x3.8mm, Pitch 1.27mm, IPC High Density)
footprint SOIC-SN8_M (SOIC, 8-Leads, Body 4.9x3.8mm, Pitch 1.27mm, IPC Low Density)
pins: 1 ~{CS} (in), 2 SO (hiz), 3 ~{WP} (in), 4 VSS (power), 5 SI (in), 6 SCK (in), 7 ~{HOLD} (in), 8 VCC (power)

## 25LC512T-E/MF
designator U?
512 Kbit SPI Bus Serial EEPROM, 8-Pin DFN, Extended Temperature, Tape and Reel
footprint DFNS-MF8_PS (SON, 8-Leads, Body 5x6mm, Pitch 1.27mm)
pins: 1 ~{CS} (in), 2 SO (hiz), 3 ~{WP} (in), 4 VSS (power), 5 SI (in), 6 SCK (in), 7 ~{HOLD} (in), 8 VCC (power), 9 EP

## 25LC512T-E/SM
designator U?
512 Kbit SPI Bus Serial EEPROM, 8-Pin SOIC, Extended Temperature, Tape and Reel
footprint SOIJ-SM8_N (SOP, 8-Leads, Body 5.2x5.2mm, Pitch 1.27mm, IPC Medium Density)
footprint SOIJ-SM8_L (SOP, 8-Leads, Body 5.2x5.2mm, Pitch 1.27mm, IPC High Density)
footprint SOIJ-SM8_M (SOP, 8-Leads, Body 5.2x5.2mm, Pitch 1.27mm, IPC Low Density)
pins: 1 ~{CS} (in), 2 SO (hiz), 3 ~{WP} (in), 4 VSS (power), 5 SI (in), 6 SCK (in), 7 ~{HOLD} (in), 8 VCC (power)

## 25LC512T-E/SN
designator U?
512 Kbit SPI Bus Serial EEPROM, 8-Pin SOIC, Extended Temperature, Tape and Reel
footprint SOIC-SN8_N (SOIC, 8-Leads, Body 4.9x3.8mm, Pitch 1.27mm, IPC Medium Density)
footprint SOIC-SN8_L (SOIC, 8-Leads, Body 4.9x3.8mm, Pitch 1.27mm, IPC High Density)
footprint SOIC-SN8_M (SOIC, 8-Leads, Body 4.9x3.8mm, Pitch 1.27mm, IPC Low Density)
pins: 1 ~{CS} (in), 2 SO (hiz), 3 ~{WP} (in), 4 VSS (power), 5 SI (in), 6 SCK (in), 7 ~{HOLD} (in), 8 VCC (power)

## 25LC512T-I/MF
designator U?
512 Kbit SPI Bus Serial EEPROM, 8-Pin DFN, Industrial Temperature, Tape and Reel
footprint DFNS-MF8_PS (SON, 8-Leads, Body 5x6mm, Pitch 1.27mm)
pins: 1 ~{CS} (in), 2 SO (hiz), 3 ~{WP} (in), 4 VSS (power), 5 SI (in), 6 SCK (in), 7 ~{HOLD} (in), 8 VCC (power), 9 EP

## 25LC512T-I/SM
designator U?
512 Kbit SPI Bus Serial EEPROM, 8-Pin SOIC, Industrial Temperature, Tape and Reel
footprint SOIJ-SM8_N (SOP, 8-Leads, Body 5.2x5.2mm, Pitch 1.27mm, IPC Medium Density)
footprint SOIJ-SM8_L (SOP, 8-Leads, Body 5.2x5.2mm, Pitch 1.27mm, IPC High Density)
footprint SOIJ-SM8_M (SOP, 8-Leads, Body 5.2x5.2mm, Pitch 1.27mm, IPC Low Density)
pins: 1 ~{CS} (in), 2 SO (hiz), 3 ~{WP} (in), 4 VSS (power), 5 SI (in), 6 SCK (in), 7 ~{HOLD} (in), 8 VCC (power)

## 25LC512T-I/SN
designator U?
512 Kbit SPI Bus Serial EEPROM, 8-Pin SOIC, Industrial Temperature, Tape and Reel
footprint SOIC-SN8_N (SOIC, 8-Leads, Body 4.9x3.8mm, Pitch 1.27mm, IPC Medium Density)
footprint SOIC-SN8_L (SOIC, 8-Leads, Body 4.9x3.8mm, Pitch 1.27mm, IPC High Density)
footprint SOIC-SN8_M (SOIC, 8-Leads, Body 4.9x3.8mm, Pitch 1.27mm, IPC Low Density)
pins: 1 ~{CS} (in), 2 SO (hiz), 3 ~{WP} (in), 4 VSS (power), 5 SI (in), 6 SCK (in), 7 ~{HOLD} (in), 8 VCC (power)

## 25LC640A-E/MF
designator U?
64K SPI Bus Serial EEPROM, 8-Pin DFN, Extended Temperature
footprint DFNS-MF8_PS (SON, 8-Leads, Body 5x6mm, Pitch 1.27mm)
pins: 1 ~{CS} (in), 2 SO (hiz), 3 ~{WP} (in), 4 VSS (power), 5 SI (in), 6 SCK (in), 7 ~{HOLD} (in), 8 VCC (power), 9 EP

## 25LC640A-E/MS
designator U?
64K SPI Bus Serial EEPROM, 8-Pin MSOP, Extended Temperature
footprint MSOP-MS8_N (TSOP, 8-Leads, Body 3x3mm, Pitch 0.65mm, IPC Medium Density)
footprint MSOP-MS8_L (TSOP, 8-Leads, Body 3x3mm, Pitch 0.65mm, IPC High Density)
footprint MSOP-MS8_M (TSOP, 8-Leads, Body 3x3mm, Pitch 0.65mm, IPC Low Density)
pins: 1 ~{CS} (in), 2 SO (hiz), 3 ~{WP} (in), 4 VSS (power), 5 SI (in), 6 SCK (in), 7 ~{HOLD} (in), 8 VCC (power)

## 25LC640A-E/P
designator U?
64K SPI Bus Serial EEPROM, 8-Pin PDIP, Extended Temperature
footprint PDIP300-P8 (DIP, 8-Leads, Row Spacing 7.62mm, Pitch 2.54mm, Body 9.5x6.6mm)
pins: 1 ~{CS} (in), 2 SO (hiz), 3 ~{WP} (in), 4 VSS (power), 5 SI (in), 6 SCK (in), 7 ~{HOLD} (in), 8 VCC (power)

## 25LC640A-E/SN
designator U?
64K SPI Bus Serial EEPROM, 8-Pin SOIC, Extended Temperature
footprint SOIC-SN8_N (SOIC, 8-Leads, Body 4.9x3.8mm, Pitch 1.27mm, IPC Medium Density)
footprint SOIC-SN8_L (SOIC, 8-Leads, Body 4.9x3.8mm, Pitch 1.27mm, IPC High Density)
footprint SOIC-SN8_M (SOIC, 8-Leads, Body 4.9x3.8mm, Pitch 1.27mm, IPC Low Density)
pins: 1 ~{CS} (in), 2 SO (hiz), 3 ~{WP} (in), 4 VSS (power), 5 SI (in), 6 SCK (in), 7 ~{HOLD} (in), 8 VCC (power)

## 25LC640A-E/ST
designator U?
64K SPI Bus Serial EEPROM, 8-Pin TSSOP, Extended Temperature
footprint TSSOP-ST8_N (TSOP, 8-Leads, Body 3x4.4mm, Pitch 0.65mm, IPC Medium Density)
footprint TSSOP-ST8_L (TSOP, 8-Leads, Body 3x4.4mm, Pitch 0.65mm, IPC High Density)
footprint TSSOP-ST8_M (TSOP, 8-Leads, Body 3x4.4mm, Pitch 0.65mm, IPC Low Density)
pins: 1 ~{CS} (in), 2 SO (hiz), 3 ~{WP} (in), 4 VSS (power), 5 SI (in), 6 SCK (in), 7 ~{HOLD} (in), 8 VCC (power)

## 25LC640A-H/SN
designator U?
64K SPI Bus Serial EEPROM, 8-Pin SOIC, Extended (High) Temperature
footprint SOIC-SN8_N (SOIC, 8-Leads, Body 4.9x3.8mm, Pitch 1.27mm, IPC Medium Density)
footprint SOIC-SN8_L (SOIC, 8-Leads, Body 4.9x3.8mm, Pitch 1.27mm, IPC High Density)
footprint SOIC-SN8_M (SOIC, 8-Leads, Body 4.9x3.8mm, Pitch 1.27mm, IPC Low Density)
pins: 1 ~{CS} (in), 2 SO (hiz), 3 ~{WP} (in), 4 VSS (power), 5 SI (in), 6 SCK (in), 7 ~{HOLD} (in), 8 VCC (power)

## 25LC640A-I/MF
designator U?
64K SPI Bus Serial EEPROM, 8-Pin DFN, Industrial Temperature
footprint DFNS-MF8_PS (SON, 8-Leads, Body 5x6mm, Pitch 1.27mm)
pins: 1 ~{CS} (in), 2 SO (hiz), 3 ~{WP} (in), 4 VSS (power), 5 SI (in), 6 SCK (in), 7 ~{HOLD} (in), 8 VCC (power), 9 EP

## 25LC640A-I/MS
designator U?
64K SPI Bus Serial EEPROM, 8-Pin MSOP, Industrial Temperature
footprint MSOP-MS8_N (TSOP, 8-Leads, Body 3x3mm, Pitch 0.65mm, IPC Medium Density)
footprint MSOP-MS8_L (TSOP, 8-Leads, Body 3x3mm, Pitch 0.65mm, IPC High Density)
footprint MSOP-MS8_M (TSOP, 8-Leads, Body 3x3mm, Pitch 0.65mm, IPC Low Density)
pins: 1 ~{CS} (in), 2 SO (hiz), 3 ~{WP} (in), 4 VSS (power), 5 SI (in), 6 SCK (in), 7 ~{HOLD} (in), 8 VCC (power)

## 25LC640A-I/P
designator U?
64K SPI Bus Serial EEPROM, 8-Pin PDIP, Industrial Temperature
footprint PDIP300-P8 (DIP, 8-Leads, Row Spacing 7.62mm, Pitch 2.54mm, Body 9.5x6.6mm)
pins: 1 ~{CS} (in), 2 SO (hiz), 3 ~{WP} (in), 4 VSS (power), 5 SI (in), 6 SCK (in), 7 ~{HOLD} (in), 8 VCC (power)

## 25LC640A-I/SN
designator U?
64K SPI Bus Serial EEPROM, 8-Pin SOIC, Industrial Temperature
footprint SOIC-SN8_N (SOIC, 8-Leads, Body 4.9x3.8mm, Pitch 1.27mm, IPC Medium Density)
footprint SOIC-SN8_L (SOIC, 8-Leads, Body 4.9x3.8mm, Pitch 1.27mm, IPC High Density)
footprint SOIC-SN8_M (SOIC, 8-Leads, Body 4.9x3.8mm, Pitch 1.27mm, IPC Low Density)
pins: 1 ~{CS} (in), 2 SO (hiz), 3 ~{WP} (in), 4 VSS (power), 5 SI (in), 6 SCK (in), 7 ~{HOLD} (in), 8 VCC (power)

## 25LC640A-I/ST
designator U?
64K SPI Bus Serial EEPROM, 8-Pin TSSOP, Industrial Temperature
footprint TSSOP-ST8_N (TSOP, 8-Leads, Body 3x4.4mm, Pitch 0.65mm, IPC Medium Density)
footprint TSSOP-ST8_L (TSOP, 8-Leads, Body 3x4.4mm, Pitch 0.65mm, IPC High Density)
footprint TSSOP-ST8_M (TSOP, 8-Leads, Body 3x4.4mm, Pitch 0.65mm, IPC Low Density)
pins: 1 ~{CS} (in), 2 SO (hiz), 3 ~{WP} (in), 4 VSS (power), 5 SI (in), 6 SCK (in), 7 ~{HOLD} (in), 8 VCC (power)

## 25LC640AT-E/MF
designator U?
64K SPI Bus Serial EEPROM, 8-Pin DFN, Extended Temperature, Tape and Reel
footprint DFNS-MF8_PS (SON, 8-Leads, Body 5x6mm, Pitch 1.27mm)
pins: 1 ~{CS} (in), 2 SO (hiz), 3 ~{WP} (in), 4 VSS (power), 5 SI (in), 6 SCK (in), 7 ~{HOLD} (in), 8 VCC (power), 9 EP

## 25LC640AT-E/MNY
designator U?
64K SPI Bus Serial EEPROM, 8-Pin TDFN, Extended Temperature, Tape and Reel
footprint TDFN-MN8 (SON, 8-Leads, Body 2x3mm, Pitch 0.5mm, Microchip Recommended)
pins: 1 ~{CS} (in), 2 SO (hiz), 3 ~{WP} (in), 4 VSS (power), 5 SI (in), 6 SCK (in), 7 ~{HOLD} (in), 8 VCC (power), 9 EP

## 25LC640AT-E/MS
designator U?
64K SPI Bus Serial EEPROM, 8-Pin MSOP, Extended Temperature, Tape and Reel
footprint MSOP-MS8_N (TSOP, 8-Leads, Body 3x3mm, Pitch 0.65mm, IPC Medium Density)
footprint MSOP-MS8_L (TSOP, 8-Leads, Body 3x3mm, Pitch 0.65mm, IPC High Density)
footprint MSOP-MS8_M (TSOP, 8-Leads, Body 3x3mm, Pitch 0.65mm, IPC Low Density)
pins: 1 ~{CS} (in), 2 SO (hiz), 3 ~{WP} (in), 4 VSS (power), 5 SI (in), 6 SCK (in), 7 ~{HOLD} (in), 8 VCC (power)

## 25LC640AT-E/SN
designator U?
64K SPI Bus Serial EEPROM, 8-Pin SOIC, Extended Temperature, Tape and Reel
footprint SOIC-SN8_N (SOIC, 8-Leads, Body 4.9x3.8mm, Pitch 1.27mm, IPC Medium Density)
footprint SOIC-SN8_L (SOIC, 8-Leads, Body 4.9x3.8mm, Pitch 1.27mm, IPC High Density)
footprint SOIC-SN8_M (SOIC, 8-Leads, Body 4.9x3.8mm, Pitch 1.27mm, IPC Low Density)
pins: 1 ~{CS} (in), 2 SO (hiz), 3 ~{WP} (in), 4 VSS (power), 5 SI (in), 6 SCK (in), 7 ~{HOLD} (in), 8 VCC (power)

## 25LC640AT-E/ST
designator U?
64K SPI Bus Serial EEPROM, 8-Pin TSSOP, Extended Temperature, Tape and Reel
footprint TSSOP-ST8_N (TSOP, 8-Leads, Body 3x4.4mm, Pitch 0.65mm, IPC Medium Density)
footprint TSSOP-ST8_L (TSOP, 8-Leads, Body 3x4.4mm, Pitch 0.65mm, IPC High Density)
footprint TSSOP-ST8_M (TSOP, 8-Leads, Body 3x4.4mm, Pitch 0.65mm, IPC Low Density)
pins: 1 ~{CS} (in), 2 SO (hiz), 3 ~{WP} (in), 4 VSS (power), 5 SI (in), 6 SCK (in), 7 ~{HOLD} (in), 8 VCC (power)

## 25LC640AT-H/SN
designator U?
64K SPI Bus Serial EEPROM, 8-Pin SOIC, Extended (High) Temperature, Tape and Reel
footprint SOIC-SN8_N (SOIC, 8-Leads, Body 4.9x3.8mm, Pitch 1.27mm, IPC Medium Density)
footprint SOIC-SN8_L (SOIC, 8-Leads, Body 4.9x3.8mm, Pitch 1.27mm, IPC High Density)
footprint SOIC-SN8_M (SOIC, 8-Leads, Body 4.9x3.8mm, Pitch 1.27mm, IPC Low Density)
pins: 1 ~{CS} (in), 2 SO (hiz), 3 ~{WP} (in), 4 VSS (power), 5 SI (in), 6 SCK (in), 7 ~{HOLD} (in), 8 VCC (power)

## 25LC640AT-I/MF
designator U?
64K SPI Bus Serial EEPROM, 8-Pin DFN, Industrial Temperature, Tape and Reel
footprint DFNS-MF8_PS (SON, 8-Leads, Body 5x6mm, Pitch 1.27mm)
pins: 1 ~{CS} (in), 2 SO (hiz), 3 ~{WP} (in), 4 VSS (power), 5 SI (in), 6 SCK (in), 7 ~{HOLD} (in), 8 VCC (power), 9 EP

## 25LC640AT-I/MNY
designator U?
64K SPI Bus Serial EEPROM, 8-Pin TDFN, Industrial Temperature, Tape and Reel
footprint TDFN-MN8 (SON, 8-Leads, Body 2x3mm, Pitch 0.5mm, Microchip Recommended)
pins: 1 ~{CS} (in), 2 SO (hiz), 3 ~{WP} (in), 4 VSS (power), 5 SI (in), 6 SCK (in), 7 ~{HOLD} (in), 8 VCC (power), 9 EP

## 25LC640AT-I/MS
designator U?
64K SPI Bus Serial EEPROM, 8-Pin MSOP, Industrial Temperature, Tape and Reel
footprint MSOP-MS8_N (TSOP, 8-Leads, Body 3x3mm, Pitch 0.65mm, IPC Medium Density)
footprint MSOP-MS8_L (TSOP, 8-Leads, Body 3x3mm, Pitch 0.65mm, IPC High Density)
footprint MSOP-MS8_M (TSOP, 8-Leads, Body 3x3mm, Pitch 0.65mm, IPC Low Density)
pins: 1 ~{CS} (in), 2 SO (hiz), 3 ~{WP} (in), 4 VSS (power), 5 SI (in), 6 SCK (in), 7 ~{HOLD} (in), 8 VCC (power)

## 25LC640AT-I/SN
designator U?
64K SPI Bus Serial EEPROM, 8-Pin SOIC, Industrial Temperature, Tape and Reel
footprint SOIC-SN8_N (SOIC, 8-Leads, Body 4.9x3.8mm, Pitch 1.27mm, IPC Medium Density)
footprint SOIC-SN8_L (SOIC, 8-Leads, Body 4.9x3.8mm, Pitch 1.27mm, IPC High Density)
footprint SOIC-SN8_M (SOIC, 8-Leads, Body 4.9x3.8mm, Pitch 1.27mm, IPC Low Density)
pins: 1 ~{CS} (in), 2 SO (hiz), 3 ~{WP} (in), 4 VSS (power), 5 SI (in), 6 SCK (in), 7 ~{HOLD} (in), 8 VCC (power)

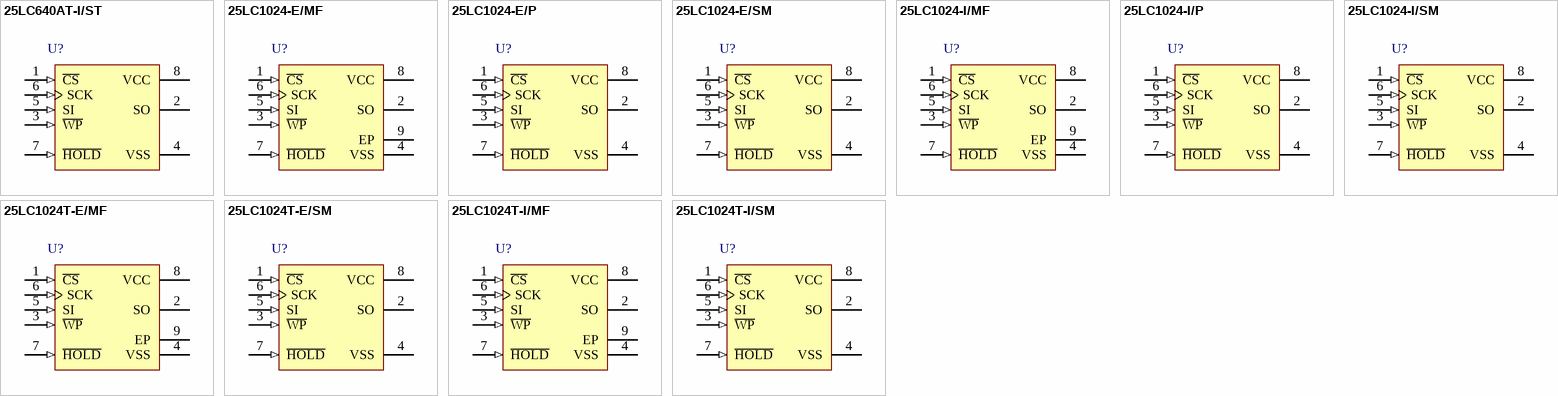
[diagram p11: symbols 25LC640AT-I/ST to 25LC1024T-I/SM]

## 25LC640AT-I/ST
designator U?
64K SPI Bus Serial EEPROM, 8-Pin TSSOP, Industrial Temperature, Tape and Reel
footprint TSSOP-ST8_N (TSOP, 8-Leads, Body 3x4.4mm, Pitch 0.65mm, IPC Medium Density)
footprint TSSOP-ST8_L (TSOP, 8-Leads, Body 3x4.4mm, Pitch 0.65mm, IPC High Density)
footprint TSSOP-ST8_M (TSOP, 8-Leads, Body 3x4.4mm, Pitch 0.65mm, IPC Low Density)
pins: 1 ~{CS} (in), 2 SO (hiz), 3 ~{WP} (in), 4 VSS (power), 5 SI (in), 6 SCK (in), 7 ~{HOLD} (in), 8 VCC (power)

## 25LC1024-E/MF
designator U?
1 Mbit SPI Bus Serial EEPROM, 8-Pin DFN, Extended Temperature
footprint DFNS-MF8_PS (SON, 8-Leads, Body 5x6mm, Pitch 1.27mm)
pins: 1 ~{CS} (in), 2 SO (hiz), 3 ~{WP} (in), 4 VSS (power), 5 SI (in), 6 SCK (in), 7 ~{HOLD} (in), 8 VCC (power), 9 EP

## 25LC1024-E/P
designator U?
1 Mbit SPI Bus Serial EEPROM, 8-Pin PDIP, Extended Temperature
footprint PDIP300-P8 (DIP, 8-Leads, Row Spacing 7.62mm, Pitch 2.54mm, Body 9.5x6.6mm)
pins: 1 ~{CS} (in), 2 SO (hiz), 3 ~{WP} (in), 4 VSS (power), 5 SI (in), 6 SCK (in), 7 ~{HOLD} (in), 8 VCC (power)

## 25LC1024-E/SM
designator U?
1 Mbit SPI Bus Serial EEPROM, 8-Pin SOIC, Extended Temperature
footprint SOIJ-SM8_N (SOP, 8-Leads, Body 5.2x5.2mm, Pitch 1.27mm, IPC Medium Density)
footprint SOIJ-SM8_L (SOP, 8-Leads, Body 5.2x5.2mm, Pitch 1.27mm, IPC High Density)
footprint SOIJ-SM8_M (SOP, 8-Leads, Body 5.2x5.2mm, Pitch 1.27mm, IPC Low Density)
pins: 1 ~{CS} (in), 2 SO (hiz), 3 ~{WP} (in), 4 VSS (power), 5 SI (in), 6 SCK (in), 7 ~{HOLD} (in), 8 VCC (power)

## 25LC1024-I/MF
designator U?
1 Mbit SPI Bus Serial EEPROM, 8-Pin DFN, Industrial Temperature
footprint DFNS-MF8_PS (SON, 8-Leads, Body 5x6mm, Pitch 1.27mm)
pins: 1 ~{CS} (in), 2 SO (hiz), 3 ~{WP} (in), 4 VSS (power), 5 SI (in), 6 SCK (in), 7 ~{HOLD} (in), 8 VCC (power), 9 EP

## 25LC1024-I/P
designator U?
1 Mbit SPI Bus Serial EEPROM, 8-Pin PDIP, Industrial Temperature
footprint PDIP300-P8 (DIP, 8-Leads, Row Spacing 7.62mm, Pitch 2.54mm, Body 9.5x6.6mm)
pins: 1 ~{CS} (in), 2 SO (hiz), 3 ~{WP} (in), 4 VSS (power), 5 SI (in), 6 SCK (in), 7 ~{HOLD} (in), 8 VCC (power)

## 25LC1024-I/SM
designator U?
1 Mbit SPI Bus Serial EEPROM, 8-Pin SOIC, Industrial Temperature
footprint SOIJ-SM8_N (SOP, 8-Leads, Body 5.2x5.2mm, Pitch 1.27mm, IPC Medium Density)
footprint SOIJ-SM8_L (SOP, 8-Leads, Body 5.2x5.2mm, Pitch 1.27mm, IPC High Density)
footprint SOIJ-SM8_M (SOP, 8-Leads, Body 5.2x5.2mm, Pitch 1.27mm, IPC Low Density)
pins: 1 ~{CS} (in), 2 SO (hiz), 3 ~{WP} (in), 4 VSS (power), 5 SI (in), 6 SCK (in), 7 ~{HOLD} (in), 8 VCC (power)

## 25LC1024T-E/MF
designator U?
1 Mbit SPI Bus Serial EEPROM, 8-Pin DFN, Extended Temperature, Tape and Reel
footprint DFNS-MF8_PS (SON, 8-Leads, Body 5x6mm, Pitch 1.27mm)
pins: 1 ~{CS} (in), 2 SO (hiz), 3 ~{WP} (in), 4 VSS (power), 5 SI (in), 6 SCK (in), 7 ~{HOLD} (in), 8 VCC (power), 9 EP

## 25LC1024T-E/SM
designator U?
1 Mbit SPI Bus Serial EEPROM, 8-Pin SOIC, Extended Temperature, Tape and Reel
footprint SOIJ-SM8_N (SOP, 8-Leads, Body 5.2x5.2mm, Pitch 1.27mm, IPC Medium Density)
footprint SOIJ-SM8_L (SOP, 8-Leads, Body 5.2x5.2mm, Pitch 1.27mm, IPC High Density)
footprint SOIJ-SM8_M (SOP, 8-Leads, Body 5.2x5.2mm, Pitch 1.27mm, IPC Low Density)
pins: 1 ~{CS} (in), 2 SO (hiz), 3 ~{WP} (in), 4 VSS (power), 5 SI (in), 6 SCK (in), 7 ~{HOLD} (in), 8 VCC (power)

## 25LC1024T-I/MF
designator U?
1 Mbit SPI Bus Serial EEPROM, 8-Pin DFN, Industrial Temperature, Tape and Reel
footprint DFNS-MF8_PS (SON, 8-Leads, Body 5x6mm, Pitch 1.27mm)
pins: 1 ~{CS} (in), 2 SO (hiz), 3 ~{WP} (in), 4 VSS (power), 5 SI (in), 6 SCK (in), 7 ~{HOLD} (in), 8 VCC (power), 9 EP

## 25LC1024T-I/SM
designator U?
1 Mbit SPI Bus Serial EEPROM, 8-Pin SOIC, Industrial Temperature, Tape and Reel
footprint SOIJ-SM8_N (SOP, 8-Leads, Body 5.2x5.2mm, Pitch 1.27mm, IPC Medium Density)
footprint SOIJ-SM8_L (SOP, 8-Leads, Body 5.2x5.2mm, Pitch 1.27mm, IPC High Density)
footprint SOIJ-SM8_M (SOP, 8-Leads, Body 5.2x5.2mm, Pitch 1.27mm, IPC Low Density)
pins: 1 ~{CS} (in), 2 SO (hiz), 3 ~{WP} (in), 4 VSS (power), 5 SI (in), 6 SCK (in), 7 ~{HOLD} (in), 8 VCC (power)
